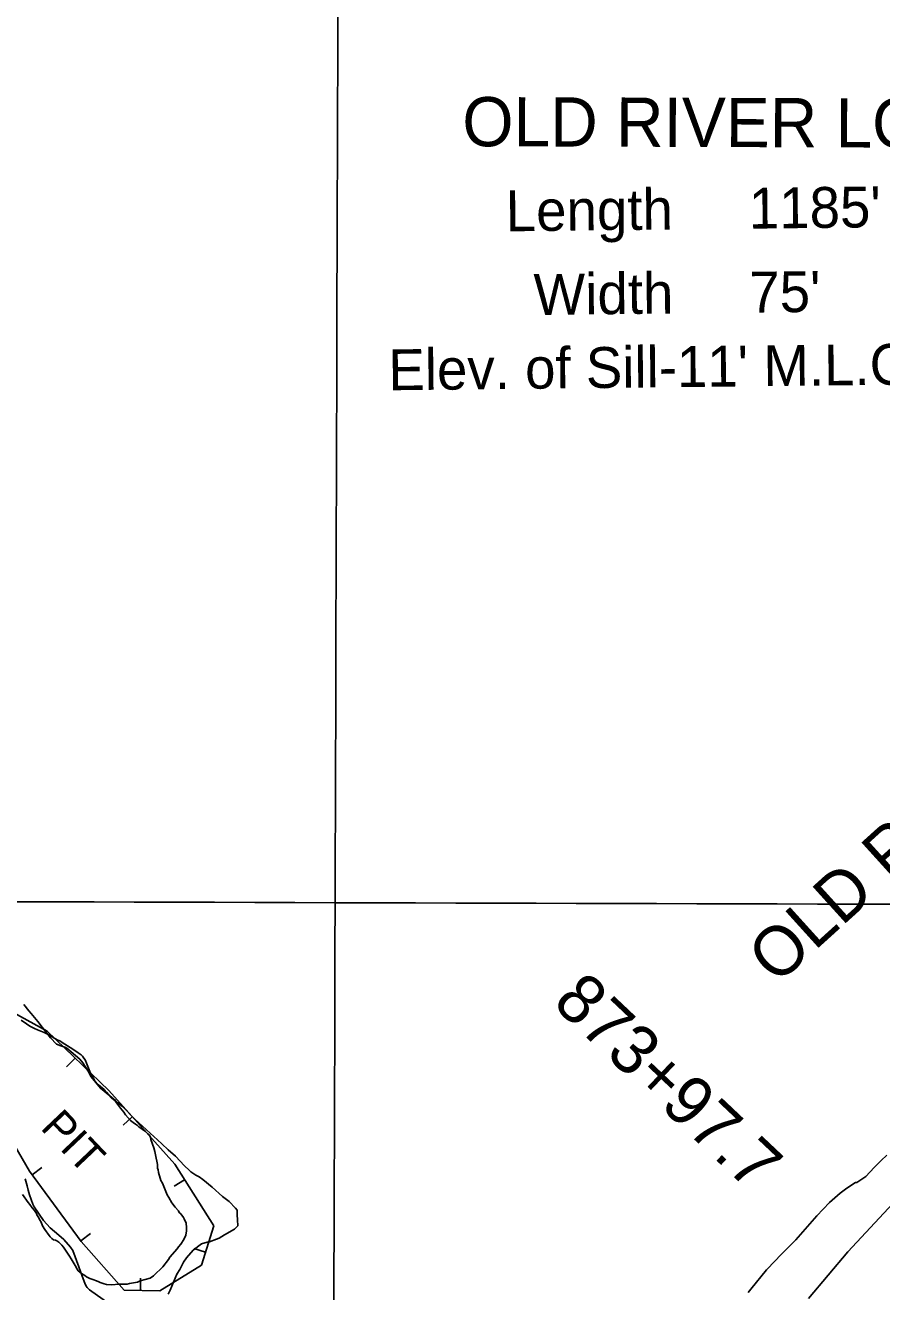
# Model space of a CAD drawing. Extents: x 3146026 to 3183936, y 897894 to 923344.
# Drawn here: x 3170529 to 3172268, y 908577 to 911149 of the extents above; entities that cross this region are included whole.
import ezdxf

# ---------------------------------------------------------------- set-up
doc = ezdxf.new("R2010")
doc.units = 0
for name, color, linetype in [('V-BORW-IDEN', 7, 'Continuous'), ('V-BORW-LINE', 7, 'Continuous'), ('V-CHAN-NAID', 7, 'Continuous'), ('V-GRID-MAJR', 7, 'Continuous'), ('V-LEVE-TOET', 7, 'Continuous'), ('V-RRAP-SILL-IDEN', 7, 'Continuous'), ('V-SITE-VEGE', 7, 'Continuous'), ('V-SURV-IDEN', 7, 'Continuous'), ('V-TOPO-SHOR', 7, 'Continuous')]:
    doc.layers.add(name, color=color, linetype=linetype)

msp = doc.modelspace()

# ---------------------------------------------------------------- linework, layer by layer
at = {"layer": 'V-BORW-LINE'}
for p, q in [((3170630.174, 909051.764), (3170612.836, 909033.7540000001)), ((3170746.403, 908932.561), (3170727.786, 908915.875)), ((3170542.8680000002, 908815.039), (3170563.002, 908829.859)), ((3170852.5870000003, 908804.716), (3170831.44, 908791.382)), ((3170641.63, 908680.868), (3170661.764, 908695.689)), ((3170895.12, 908657.719), (3170871.25, 908665.152)), ((3170762.773, 908579.792), (3170763.306, 908604.786))]:
    msp.add_line(p, q, dxfattribs=at)
for points in [[(3170573.5810000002, 909106.247), (3170458.599, 909169.236)], [(3170698.644, 908985.848), (3170573.5810000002, 909106.247)], [(3170832.657, 908836.324), (3170698.644, 908985.848)], [(3170500.116, 908886.4770000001), (3170537.474, 908822.367)], [(3170537.474, 908822.367), (3170642.577, 908679.582)], [(3170911.701, 908710.9670000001), (3170832.657, 908836.324)], [(3170886.958, 908631.509), (3170911.701, 908710.9670000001)], [(3170642.577, 908679.582), (3170729.755, 908580.496)], [(3170802.082, 908578.953), (3170886.958, 908631.509)], [(3170729.755, 908580.496), (3170802.082, 908578.953)]]:
    msp.add_lwpolyline(points, dxfattribs=at)
at = {"layer": 'V-GRID-MAJR'}
for points in [[(3171139.739, 903307.688), (3171158.249, 909367.4720000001), (3171176.767, 915430.341), (3171195.286, 921493.257), (3171195.295, 921496.294)], [(3150267.842, 909437.3570000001), (3155490.4390000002, 909418.746), (3160713.04, 909400.895), (3165935.643, 909383.804), (3171158.249, 909367.4720000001), (3176380.857, 909351.9), (3181603.467, 909337.087), (3181603.468, 909337.087)]]:
    msp.add_spline(points, degree=3, dxfattribs=at)
at = {"layer": 'V-LEVE-TOET'}
msp.add_lwpolyline([(3172119.463000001, 908563.2279999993), (3172199.220000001, 908658.1789999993), (3172309.243000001, 908776.3099999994), (3172457.342000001, 908922.7689999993), (3172598.089000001, 909075.0559999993), (3172694.252000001, 909177.2979999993), (3172867.290000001, 909358.3429999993)], dxfattribs=at)
at = {"layer": 'V-SITE-VEGE'}
for points in [[(3170818.989000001, 908572.5729999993), (3170823.105000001, 908580.3209999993), (3170836.469000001, 908612.8609999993), (3170842.645000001, 908622.1609999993), (3170850.362000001, 908637.1419999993), (3170856.539000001, 908645.9279999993), (3170869.933000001, 908661.4359999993), (3170886.944000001, 908674.3689999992), (3170898.292000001, 908677.9979999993), (3170902.937000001, 908678.5239999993), (3170917.379000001, 908683.7119999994), (3170922.538000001, 908685.7839999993), (3170933.364000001, 908693.0299999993), (3170953.989000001, 908704.4189999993), (3170960.686000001, 908711.1409999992), (3170960.149000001, 908723.5269999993), (3170959.101000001, 908733.3309999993), (3170959.084000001, 908743.1389999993), (3170955.980000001, 908747.2609999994), (3170943.0530000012, 908760.6589999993), (3170929.618000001, 908770.4449999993), (3170908.421000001, 908789.5029999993), (3170889.299000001, 908805.4699999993), (3170882.063000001, 908810.6179999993), (3170875.346000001, 908814.2189999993), (3170865.530000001, 908820.9129999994), (3170861.9110000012, 908824.0039999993), (3170852.089000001, 908833.2769999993), (3170833.991000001, 908852.8579999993), (3170818.9990000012, 908865.7359999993), (3170806.076000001, 908877.5859999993), (3170797.802000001, 908885.8289999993), (3170775.057000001, 908906.4359999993), (3170751.794000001, 908928.0729999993), (3170726.460000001, 908953.3209999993), (3170717.156000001, 908961.0459999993), (3170711.987000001, 908965.6829999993), (3170681.492000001, 908990.4039999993), (3170662.872000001, 909013.5979999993), (3170656.658000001, 909025.4569999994), (3170645.792000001, 909041.9559999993), (3170639.584000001, 909049.6869999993), (3170613.738000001, 909071.8359999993), (3170609.606000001, 909073.8949999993), (3170601.344000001, 909076.4629999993), (3170592.562000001, 909080.0569999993), (3170580.151000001, 909092.9389999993), (3170563.083000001, 909114.5879999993), (3170554.807000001, 909125.9279999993), (3170540.842000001, 909142.4209999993), (3170536.189000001, 909147.5739999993), (3170526.358000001, 909160.4619999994)], [(3172278.846000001, 908854.5439999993), (3172266.753000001, 908843.9639999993), (3172252.7860000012, 908829.6909999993), (3172235.556000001, 908811.2709999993), (3172217.437000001, 908799.3359999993), (3172215.121000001, 908798.8849999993), (3172197.002000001, 908787.4139999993), (3172183.985000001, 908777.3029999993), (3172162.123000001, 908758.4449999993), (3172136.512000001, 908731.2769999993), (3172093.656000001, 908682.9109999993), (3172079.691000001, 908668.6389999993), (3172073.176000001, 908662.6579999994), (3172062.467000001, 908651.6089999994), (3172051.756000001, 908640.0959999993), (3172034.063000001, 908621.6779999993), (3172002.368000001, 908582.5079999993), (3171997.238000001, 908575.5919999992)], [(3170528.517000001, 908806.3949999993), (3170532.670000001, 908792.4689999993), (3170534.751000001, 908783.6969999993), (3170537.864000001, 908773.8949999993), (3170544.0900000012, 908755.3259999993), (3170547.197000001, 908749.6529999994), (3170565.825000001, 908721.8149999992), (3170579.787000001, 908706.8709999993), (3170597.359000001, 908692.4489999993), (3170607.183000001, 908683.1749999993), (3170621.1440000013, 908667.7169999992), (3170625.285000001, 908661.0139999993), (3170637.731000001, 908628.0019999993), (3170644.473000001, 908608.9169999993), (3170650.174000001, 908594.4739999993), (3170652.765000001, 908588.8009999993), (3170654.836000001, 908585.7089999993), (3170659.489000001, 908581.0699999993), (3170698.763000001, 908553.2689999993)]]:
    msp.add_lwpolyline(points, dxfattribs=at)
at = {"layer": 'V-TOPO-SHOR'}
for points in [[(3170797.456000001, 908835.9439999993), (3170793.397000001, 908855.4099999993), (3170792.953000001, 908858.6519999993), (3170792.048000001, 908862.3609999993), (3170789.774000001, 908869.7789999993), (3170784.312000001, 908886.4739999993), (3170783.413000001, 908891.1089999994), (3170780.6610000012, 908895.7509999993), (3170773.294000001, 908902.7369999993), (3170759.923000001, 908912.0699999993), (3170756.697000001, 908914.8649999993), (3170753.009000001, 908917.6629999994), (3170747.936000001, 908920.9319999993), (3170742.404000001, 908925.1279999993), (3170732.748000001, 908936.7549999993), (3170729.074000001, 908941.8659999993), (3170722.176000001, 908950.2389999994), (3170712.067000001, 908963.7179999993), (3170708.845000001, 908966.9769999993), (3170703.316000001, 908971.6359999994), (3170693.655000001, 908982.3369999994), (3170691.360000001, 908985.5889999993), (3170689.058000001, 908987.9179999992), (3170678.003000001, 908997.7009999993), (3170670.177000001, 909005.6119999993), (3170664.222000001, 909016.7559999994), (3170662.387000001, 909020.0059999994), (3170658.729000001, 909027.8969999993), (3170653.248000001, 909041.3519999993), (3170651.4280000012, 909046.9139999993), (3170644.995000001, 909055.7449999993), (3170642.234000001, 909058.5389999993), (3170636.703000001, 909062.7349999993), (3170625.631000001, 909069.7409999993), (3170620.097000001, 909073.4749999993), (3170603.951000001, 909083.2869999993), (3170599.341000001, 909086.5509999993), (3170595.186000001, 909088.4269999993), (3170589.185000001, 909091.6999999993), (3170578.111000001, 909098.2429999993), (3170567.497000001, 909103.8569999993), (3170553.638000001, 909109.0259999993), (3170547.635000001, 909111.8359999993), (3170538.405000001, 909116.5179999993), (3170531.487000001, 909121.1849999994), (3170520.421000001, 909129.1169999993)], [(3170523.540000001, 908774.9789999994), (3170535.0190000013, 908758.2509999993), (3170538.241000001, 908754.5299999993), (3170543.295000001, 908748.0189999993), (3170547.893000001, 908742.4379999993), (3170551.559000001, 908735.9379999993), (3170553.390000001, 908732.2249999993), (3170555.688000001, 908728.9729999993), (3170557.973000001, 908723.8669999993), (3170561.183000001, 908718.2939999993), (3170563.923000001, 908711.3349999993), (3170568.506000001, 908703.4399999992), (3170577.700000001, 908691.8179999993), (3170579.537000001, 908689.0279999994), (3170582.756000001, 908685.3069999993), (3170586.447000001, 908682.9719999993), (3170590.143000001, 908682.0259999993), (3170593.375000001, 908680.6189999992), (3170597.064000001, 908677.8219999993), (3170603.048000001, 908671.7719999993), (3170606.728000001, 908667.5839999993), (3170610.861000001, 908661.5439999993), (3170615.907000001, 908653.6449999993), (3170619.125000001, 908649.4609999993), (3170622.338000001, 908644.3509999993), (3170628.298000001, 908634.1359999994), (3170630.129000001, 908630.4229999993), (3170634.253000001, 908622.9929999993), (3170636.549000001, 908619.7379999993), (3170643.463000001, 908614.1449999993), (3170649.922000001, 908610.4079999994), (3170653.611000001, 908607.6079999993), (3170660.072000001, 908604.3329999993), (3170666.077000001, 908601.9839999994), (3170673.931000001, 908599.1619999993), (3170678.549000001, 908597.2859999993), (3170681.318000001, 908595.8809999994), (3170689.172000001, 908593.0609999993), (3170694.256000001, 908591.6439999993), (3170704.903000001, 908591.5849999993), (3170719.258000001, 908592.4299999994), (3170730.368000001, 908592.3689999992), (3170735.924000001, 908592.7989999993), (3170740.559000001, 908593.6999999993), (3170756.775000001, 908596.3869999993), (3170762.345000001, 908599.1339999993), (3170772.544000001, 908601.8549999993), (3170782.746000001, 908605.0379999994), (3170789.252000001, 908609.6319999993), (3170794.837000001, 908615.1549999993), (3170803.676000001, 908622.9739999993), (3170806.007000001, 908625.7389999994), (3170808.333000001, 908628.0409999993), (3170819.988000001, 908642.7889999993), (3170822.790000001, 908647.4029999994), (3170837.237000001, 908664.4479999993), (3170840.034000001, 908668.1369999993), (3170845.158000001, 908674.1249999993), (3170850.766000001, 908683.3529999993), (3170854.981000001, 908692.1249999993), (3170856.418000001, 908700.9109999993), (3170856.457000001, 908707.8559999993), (3170855.581000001, 908716.6559999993), (3170851.923000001, 908725.0079999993), (3170850.0900000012, 908728.2579999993), (3170845.038000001, 908735.2289999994), (3170841.812000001, 908738.0249999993), (3170839.979000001, 908741.2769999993), (3170833.542000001, 908749.1799999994), (3170826.646000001, 908758.0129999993), (3170820.689000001, 908768.6939999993), (3170817.478000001, 908773.8029999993), (3170812.908000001, 908784.4749999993), (3170807.4280000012, 908797.9309999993), (3170804.219000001, 908803.5029999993), (3170802.853000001, 908807.6769999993), (3170799.676000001, 908819.2689999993), (3170798.781000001, 908824.8269999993), (3170797.876000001, 908828.5359999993), (3170797.456000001, 908835.9439999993)]]:
    msp.add_lwpolyline(points, dxfattribs=at)

# ---------------------------------------------------------------- texts
at = {"layer": 'V-BORW-IDEN'}
msp.add_text('PIT', height=63.99987399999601, rotation=313.49264527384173, dxfattribs=at).set_placement((3170557.8661629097, 908909.2039583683))
at = {"layer": 'V-CHAN-NAID'}
msp.add_text('OLD RIVER LOCK BRIDGE (303.8)', height=100.00000199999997, rotation=42.13753239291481, dxfattribs=at).set_placement((3172054.571439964, 909198.7948515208))
at = {"layer": 'V-RRAP-SILL-IDEN'}
for s, height, rotation, p in [('OLD RIVER LOCK', 99.99999999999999, 359.8166657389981, (3171416.37922527, 910903.8875367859)), ("Length     1185'", 82.99983200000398, 0.6296054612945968, (3171505.056953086, 910730.9295103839)), ("Width     75'", 82.99983200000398, 0.6296054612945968, (3171561.8258395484, 910561.0278501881)), ("Elev. of Sill-11' M.L.G.", 82.99983200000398, 0.6296054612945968, (3171266.7978532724, 910408.1303014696))]:
    msp.add_text(s, height=height, rotation=rotation, dxfattribs=at).set_placement(p)
at = {"layer": 'V-SURV-IDEN'}
msp.add_text('873+97.7', height=100, rotation=316.5975000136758, dxfattribs=at).set_placement((3171596.9100016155, 909161.0242051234))

doc.saveas('drawing.dxf')
